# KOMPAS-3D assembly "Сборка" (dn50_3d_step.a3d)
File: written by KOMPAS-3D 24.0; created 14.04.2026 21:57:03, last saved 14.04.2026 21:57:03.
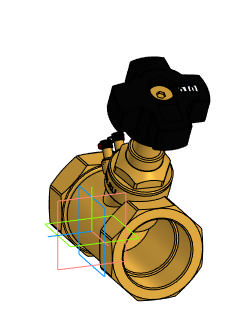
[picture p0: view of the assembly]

Document properties: Автор: tyuri; Полное имя файла: D:\Аутсорс\VB0000P-T Клапан балансировочный статический DN.ru\DN50\Исходные данные\dn50_3d_step.a3d

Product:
- Component [detail]: Деталь1  | qty 1  | Автор: tyuri; source file: Деталь1 - Деталь1.m3d
- Component [detail]: Деталь2  | qty 1  | Автор: tyuri; source file: Деталь2 - Деталь2.m3d
- Part/product: Сборка

Referenced files in D:\Аутсорс\VB0000P-T Клапан балансировочный статический DN.ru\DN50\Исходные данные\: Деталь1 - Деталь1.m3d, Деталь2 - Деталь2.m3d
